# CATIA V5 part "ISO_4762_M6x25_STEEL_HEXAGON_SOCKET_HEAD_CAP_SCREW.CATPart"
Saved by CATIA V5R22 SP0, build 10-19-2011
Part number: ISO 4762 SCREW M6x25 STEEL HEXAGON SOCKET HEAD CAP
Publications: "Mating Face", "Axis"
Bounding box of the stored display mesh (mm): x -25 to 6, y -5 to 5, z -5 to 5
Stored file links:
  D:\CAO_PER_MODIF_2025\CAO_PER_pick&place_2024P\ISO_4762_M6x25_STEEL_HEXAGON_SOCKET_HEAD_CAP_SCREW.CATPart
  C:\Program Files\Dassault Systemes\B22\win_b64\startup\components\MechanicalStandardParts\EN_Standards\Design_Tables\EN_ISO_4762_HEXAGON_SOCKET_HEAD_CAP_SCREW.txt
  C:\Program Files\Dassault Systemes\B22\win_b64\startup\components\MechanicalStandardParts\ISO_Standards\Design_Tables\ISO_4762_HEXAGON_SOCKET_HEAD_CAP_SCREW.txt
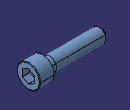
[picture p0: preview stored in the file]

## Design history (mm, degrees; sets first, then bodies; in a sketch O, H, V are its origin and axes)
Parameters
  d_dia = 6 mm
  l_nom = 25 mm
  k_head_depth_max = 6 mm
  s_nom = 5 mm
  r_min = 0.25 mm
  ds_max = 6 mm
  e = 5.723 mm
  t_min = 3 mm
  p_pitch = 1 mm
  Threading = 22 mm
  dk_max = 10 mm
Body1 "PartBody" (main body)
  Sketch1 on yz-plane, origin (0, 0, 0), H (0, 1, 0), V (0, 0, 1)
    circle A1 centre (0, 0) radius 5
    radius A1 = 5 {= dk_max /2}
  Pad1: profile Sketch1, direction (1, 0, 0), length 6 {= k_head_depth_max}
  Fillet1: radius 0.25 {= r_min}, on edge [face of Pad1 | face of Pad1]
  Body2
    Sketch2 on face of Pad1, origin (6, 0, 0), H (0, 1, 0), V (0, 0, 1)
      point P1 (2.5, -1.4434)
      point P2 (2.5, 1.4434)
      point P3 (0, 2.8868)
      point P4 (-2.5, 1.4434)
      point P5 (-2.5, -1.4434)
      point P6 (0, -2.8868)
      point P7 (2.5, 0)
      line L1 (2.5, -1.4434) -> (2.5, 1.4434)
      line L2 (2.5, 1.4434) -> (0, 2.8868)
      line L3 (0, 2.8868) -> (-2.5, 1.4434)
      line L4 (-2.5, 1.4434) -> (-2.5, -1.4434)
      line L5 (-2.5, -1.4434) -> (0, -2.8868)
      line L6 (0, -2.8868) -> (2.5, -1.4434)
      construction line L7 (0, 0) -> (2.5, 0)
      construction circle A1 centre (0, 0) radius 2.8868
      construction arc A2 centre (-2.5, -1.4434) radius 2.8868 from (-2.5, 1.4434) to (0, -2.8868) cw
      construction arc A3 centre (2.5, 1.4434) radius 2.8868 from (0, 2.8868) to (2.5, -1.4434) ccw
      point P8 (-2.5, -1.4434)
      point P9 (2.5, 1.4434)
      distance L1 L4 = 5 {= s_nom}
      horizontal: L7 H
      coincidence: A1 P1, A1 P2, A1 P3, A1 P4, A1 P5, A1 P6, A2 P4, A2 P6, A2 O, P8 P5, A3 P3, A3 P1, A3 O, P9 P2
      midpoint: P7 L1
    Pad2: profile Sketch2, direction (-1, 0, 0), length 4.6493 {= t_min +(e /3.47)}
    Body3
      Sketch3 on zx-plane, origin (0, 0, 0), H (-1, 0, 0), V (0, 0, 1)
        point P1 (-1.3479, 0)
        line L1 (-1.3479, 0) -> (-3, 2.8615)
        line L2 (-3, 2.8615) -> (-6, 2.8615)
        line L3 (-6, 2.8615) -> (-6, 0)
        axis line L4 (-46.2384, 0) -> (26.3409, 0)
        reference projected line E1 (-6, -6.9227) -> (-6, 6.9227) from edge [face of Pad2 | face of Pad2]
        length L2 = 3 {= t_min}
        angle L1 L4 = 60
        distance L2 L4 = 2.8615 {= e /2}
        horizontal: L2 H, L4 H
        perpendicularity: L3 L2
        fix: L4
        coincidence: L3 E1, P1 L4
      Shaft1: profile Sketch3, axis Sketch3.L4, angle 360
    Intersect1: tool Body3
  Remove1: tool Body2
  Sketch4 on xy-plane, origin (0, 0, 0), H (1, 0, 0), V (0, 1, 0)
    line L1 (0, 0) -> (0, 3)
    line L2 (0, 3) -> (-3, 3)
    line L3 (-3, 3) -> (-3, 2.9268)
    line L4 (-3, 2.9268) -> (-25, 2.9268)
    line L5 (-25, 2.9268) -> (-25, 0)
    axis line L6 (-192.3446, 0) -> (99.1594, 0)
    distance L5 L1 = 25 {= l_nom}
    distance L3 L5 = 22 {= Threading}
    distance L2 L6 = 3 {= ds_max /2}
    distance L4 L6 = 2.9268 {= d_dia /2.05}
    vertical: L1 V, L3 V, L5 V
    horizontal: L2 H, L4 H, L6 H
    fix: L6
  Shaft2: profile Sketch4, axis Sketch4.L6, angle 360
  Fillet2: radius 0.25 {= r_min}, on edge [face of Shaft2 | face of Pad1]
  Chamfer1: length 1 {= p_pitch}, angle 45, on edge [face of Shaft2 | face of Shaft2]
  Thread1: diameter 5.8537 {= d_dia /1.025}, depth 22 {= Threading}, pitch 1, on face of Shaft2, from face of Shaft2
